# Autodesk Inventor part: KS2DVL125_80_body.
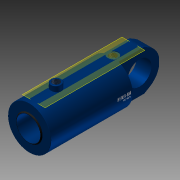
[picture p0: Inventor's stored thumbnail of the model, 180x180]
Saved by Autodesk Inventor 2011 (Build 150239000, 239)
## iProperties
Created: 2010-11
Document SubType Name: Modeling
Designer: TB
Mass: 405.061 g
Surface Area: 916.939 cm^2
Volume: 405.061 cm^3
Density: 1 g/cm^3
Author: TB
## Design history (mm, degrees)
sketch "Sketch2"
  geometry: L1 (-35, -3)-(-35, 3); L2 (-35, -9)-(-35, 9); L3 (-35, 0)-(-35, 72.5); L4 (-35, 72.5)-(-300, 72.5); L5 (-300, 72.5)-(-300, 72.5); L6 (-300, 72.5)-(-310, 72.5); L7 (-310, 72.5)-(-310, 44); L8 (-310, 44)-(-313, 41); L9 (-313, 41)-(-313, 40); L10 (-313, 40)-(-218, 40); L11 (-218, 40)-(-218, 62.5); L12 (-218, 62.5)-(-66, 62.5); L13 (-66, 62.5)-(-66, 0); L14 (-66, 0)-(-35, 0); L15 (-66, 0)-(-148.421, 0); L16 (-35, 9)-(-32, 12) reference; L17 (-32, 12)-(-35, 12) reference; L18 (-35, 12)-(-35, 9) reference; L19 (-32, 12)-(-35, 9) reference; L20 (-32, 12)-(-35, 12) reference; L21 (-35, 9)-(-35, 12) reference; L22 (-35, 9)-(-32, 12) reference; 1 further point
  constraints: 44 end point, 8 perpendicular, 6 parallel, 5 collinear, 2 horizontal, 2 vertical, 1 coincident, 1 midpoint, 1 point on line, 10 other
  dimensions: "DiaY" = 145 diameter of L4 L15; "DiaI" = 125 diameter of L12 L15; "d4" = 1 distance of L8.end L9.end; "d5" = 45 deg angle of L10 L8; "d6" = 3 distance between parallel lines of L7 L9; "DiaStang" = 80 diameter of L10 L15; "RindDia" = 145 diameter of L6 L15; "RingLengde" = 10 distance of L5.end L6.end; "RingTykk" = 92 distance between parallel lines of L11 L7; "KroppLengde" = 275 distance between parallel lines of L7 L3 (derived); "BunnTykkelse" = 31 distance between parallel lines of L13 L3
revolve "Kropp" sketch "Sketch2" stored, may be unused: angle "d13" = 90 deg
sketch "Sketch3"
  geometry: L1 (-66, -62.5)-(-66, 62.5) reference; L2 (-66, 0.01)-(-166, 0.01); L3 (-166, -0.01)-(-66, -0.01); A1 r 0.01 centre (-166, 0) between (-166, 0.01) and (-166, -0.01); A2 r 0.01 centre (-66, 0) between (-66, -0.01) and (-66, 0.01); 2 further points
  constraints: 4 end point, 4 point on circle, 4 tangent, 2 centre point, 1 coincident, 1 midpoint, 1 parallel, 1 perpendicular
  dimensions: "d17" = 0.01 radius of A2; "d18" = 100 distance of L2.start L2.end (= Slaglengde)
feature "BaneTransitionalConstraint" sketch "Sketch3" dims "d19" = 2, "d20" = 0
sketch "Sketch6"
  geometry: L1 (-101.5, 0)-(101.5, 0) reference; L2 (14.671, 71)-(-11.843, 71); L3 (72.5, 0)-(72.5, 31.248); L4 (-72.5, 0)-(-72.5, -18.451); A1 r 72.5 centre (0, 0) between (-72.5, 0) and (72.5, 0) reference; 2 further points
  constraints: 6 end point, 2 point on circle, 2 vertical, 2 other
  dimensions: "d30" = 71 distance from line of point (0, 0) L2 (computed from DiaY); "d31" = 0 deg angle of L1 L2 (computed from Vinkel_Plussport); "d37" = 90 deg angle of L2 L3; "d38" = 90 deg angle of L2 L4
  node "Projected Loop3"
workplane "Work Plane5"
sketch "Sketch7"
  geometry: L1 (14.671, -375.6)-(14.671, 62.6) reference; L2 (-19.633, -35)-(38.367, -35) reference; C1 r 17.5 at (14.671, -52.5); 1 further point
  constraints: 1 centre point, 1 point on line
  dimensions: "PortDia" = 35 diameter of C1
extrude "Extrusion2" cut sketch "Sketch7" stored distance "d34" = 1.5; taper "d35" = 0 deg
workplane "Work Plane7"
sketch "Sketch4"
  geometry: L1 (-16.68, -40)-(-16.68, -78.777); L2 (-16.68, -78.777)-(16.68, -78.777); L3 (16.68, -78.777)-(16.68, -40); L4 (16.68, -40)-(-16.68, -40); L5 (-40.643, -40)-(0, -40); L6 (-29, -35)-(29, -35); L7 (0, -35)-(0, -40); 2 further points
  constraints: 6 end point, 2 midpoint, 2 other
  dimensions: "d40" = 5 distance of L7.start L5.end
emboss "Emboss1" sketch "Sketch4" dims "d4" = 1, "d5" = 45 deg, "d6" = 3, "d22" = 0.2, "d23" = 0, "DiaI" = 125, "DiaY" = 145, "RindDia" = 145, "DiaStang" = 80, "RingTykk" = 92, "RingLengde" = 10, "KroppLengde" = 275 (derived), "BunnTykkelse" = 31
workplane "Work Plane8"
sketch "Sketch8"
  geometry: L1 (-29, -35)-(29, -35); L2 (0, -35)-(0, -40); L3 (-5.906, -110.587)-(-5.906, -40); L4 (-5.906, -40)-(5.906, -40); L5 (5.906, -40)-(5.906, -110.587); L6 (5.906, -110.587)-(-5.906, -110.587); L7 (72.5, -35)-(-72.5, -35); L8 (72.5, -35)-(-72.5, -35) reference; 3 further points
  constraints: 6 end point, 4 midpoint, 2 other
  dimensions: "d42" = 5 distance of L2.start L2.end
emboss "Emboss2" sketch "Sketch8" dims "d4" = 1, "d5" = 45 deg, "d6" = 3, "d43" = 0.2, "d44" = 0, "DiaI" = 125, "DiaY" = 145, "RindDia" = 145, "DiaStang" = 80, "RingTykk" = 92, "RingLengde" = 10, "KroppLengde" = 275 (derived), "BunnTykkelse" = 31
sketch "Sketch9"
  geometry: A1 r 12.5 centre (9.367, -52.5) between (0, -60.776) and (18.735, -60.776) reference; 1 further point
hole "Hole1" sketch "Sketch9" at (9.367, -52.5) diameter "d45" = 14.95; stored, may be unused: countersink angle "d49" = 82 deg, drill point angle "d51" = 118 deg; dims "d46" = 6, "d47" = 3.023, "d48" = 2, "DiaInvPluss" = 24.5
workplane "Work Plane9"
sketch "Sketch10"
  geometry: L1 (-101.5, 0)-(101.5, 0) reference; L2 (0, 72.5)-(13.136, 72.5); L3 (0, 72.5)-(0, 31.79); L4 (17.5, 70.356)-(17.5, 90); L5 (17.5, 90)-(0, 90); L6 (0, 90)-(0, 72.5); L7 (0, 72.5)-(17.5, 70.356); C1 r 72.5 at (0, 0) reference; A1 r 72.5 centre (0, 0) between (0, 72.5) and (17.5, 70.356); 1 further point
  constraints: 12 end point, 4 perpendicular, 2 concentric, 2 point on circle, 1 centre point, 1 point on line, 1 tangent
  dimensions: "d53" = 0 deg angle of L1 L2 (computed from Vinkel_Minusport); "DiaUtvStussMinus" = 35 diameter of L4 L3; "HøydeStussMinuss" = 17.5 distance between parallel lines of L2 L5
revolve "Revolution2" sketch "Sketch10" stored, may be unused: angle "d56" = 90 deg
hole "Hole2" diameter "d59" = 24.117; stored, may be unused: countersink angle "d63" = 82 deg, drill point angle "d65" = 118 deg; dims "d57" = 10, "d58" = 10, "d60" = 6, "d61" = 3.023, "d62" = 2, "DiaInvStussMinus" = 24.5
fillet "Fillet1" dims "d66" = 2
sketch "Sketch15"
  geometry: L1 (25, -68.053)-(25, 68.053); L2 (-25, -68.053)-(-25, 68.053); L3 (0, 101.5)-(0, -101.5) reference; A1 r 72.5 centre (0, 0) between (25, -68.053) and (-25, -68.053) reference; A2 r 72.5 centre (0, 0) between (25, 68.053) and (-25, 68.053); A3 r 72.5 centre (0, 0) between (-25, -68.053) and (25, -68.053)
  constraints: 8 point on circle, 4 end point, 4 point on line, 2 centre point, 2 concentric, 2 parallel, 1 coincident
  dimensions: "EyeBunnTykk" = 25 distance from line of L1 A1.centre; "EyeBunnTykk2" = 25 distance from line of A1.centre L2
extrude "Extrusion6" join sketch "Sketch15" taper "d98" = 0 deg; distance "LengdeEyeMinussBunntykk" = 136
sketch "Sketch16"
  geometry: L1 (-309, 72.5)-(101, 72.5) reference; L2 (-309, -72.5)-(101, -72.5) reference; L3 (-309, 72.5)-(101, 72.5) reference; L4 (101, 72.5)-(101, 68.053) reference; L5 (101, -68.053)-(101, 68.053) reference; L6 (-393.672, 0)-(199.03, 0) reference; L7 (36.5, 72.5)-(101, 72.5); L8 (101, 72.5)-(101, 8); A1 r 64.5 centre (36.5, 8) between (101, 8) and (36.5, 72.5); 6 further points; 2 other entities
  constraints: 4 end point, 4 tangent, 2 point on circle, 2 point on line, 1 centre point, 1 collinear, 1 perpendicular, 2 other
  dimensions: "d137" = 8 distance from line of L8.end L6
extrude "Extrusion7" cut sketch "Sketch16" taper "d102" = 0 deg; stored distance "ExtruEyeBunn" = 50
mirror "Mirror1"
sketch "Sketch20"
  geometry: L1 (-309, 72.5)-(101, 72.5) reference; L2 (101, -68.053)-(101, 68.053) reference; L3 (101, 72.5)-(101, 68.053) reference; L4 (-391.89, 0)-(188.338, 0) reference; L5 (-35, -68.053)-(-35, 68.053) reference; L6 (-35, 0)-(36, 0); L7 (36, 0)-(36, 20.918); L8 (69.354, 57.771)-(50.804, 68.481); A1 r 66.708 centre (36, 0) between (101, 15) and (69.354, 57.771); A2 r 35 centre (43.843, 37.5) between (43.843, 72.5) and (43.843, 72.5); A3 r 30 centre (35.804, 42.5) between (50.804, 68.481) and (35.804, 72.5); 1 further point
  constraints: 6 end point, 6 point on circle, 5 point on line, 4 tangent, 3 centre point, 1 coincident, 1 midpoint, 1 perpendicular
  dimensions: "d147" = 71 distance of L6.start L6.end; "d157" = 15 distance from line of L4 A1.start; "d158" = 30 deg angle of L1 L8; "d160" = 30 radius of A3
extrude "Extrusion10" cut sketch "Sketch20" stored distance "d144" = 10; taper "d145" = 0 deg
mirror "Mirror2"
sketch "Sketch17"
  geometry: L1 (136.107, 0)-(0, 0) reference; L2 (68.053, -360.8)-(68.053, 218.8) reference; C1 r 40 at (68.053, 71); 1 further point
  constraints: 1 centre point, 1 point on line
  dimensions: "DiaHullEyeBunn" = 80 diameter of C1; "d125" = 71 distance from line of C1.centre L1
extrude "Extrusion8" cut sketch "Sketch17" taper "d105" = 0 deg; distance "ExtruHullEye" = 50
pattern_circular "Circular Pattern1 Only Subsea" dims "d108" = 180 deg (derived)
workplane "Work Plane11"
sketch "Sketch18"
  geometry: L1 (0, -79.2)-(0, 13.2) reference; L2 (62.5, -66)-(-62.5, -66) reference; L3 (62.5, -66)-(-62.5, -66) reference; C1 r 17.5 at (0, -29); 1 further point
  constraints: 1 centre point
  dimensions: "DiaForsenkPlussPort" = 35 diameter of C1; "PlassPlussport" = 37 distance from line of L2 C1.centre
extrude "Extrusion9" cut sketch "Sketch18" stored distance "d113" = 10; taper "d114" = 0 deg
sketch "Sketch19"
  geometry: 10 further points
  constraints: 1 other
hole "Hole3" sketch "Sketch19" at (0, -29) diameter "d115" = 24.117; stored, may be unused: countersink angle "d119" = 90 deg, drill point angle "d121" = 118 deg; dims "d116" = 6, "d117" = 4, "d118" = 2, "d120" = 14.5
pattern_circular "Circular Pattern2 Only Subsea" dims angle "d123" = 360 deg
body "Solid1"
chamfer "Chamfer" distance "Chamfer" = 1; stored, may be unused: second distance "d15" = 2, angle "d16" = 45 deg
node "Projected Loop2"
body "Srf1"
node "Projected Loop10"
other parameters: "Slaglengde" = 100, "Forlengelse_rør" = 0, "Vinkel_Plussport" = 0 [user parameter; used in 1 equation term], "Vinkel_Minusport" = 0, "d32" = 90 deg, "d39" = 90 deg, "d41" = 90 deg, "Minusport2" = 180 deg, "ForsenkningPlussPort" = 70.7 (derived), "EyeLengdeUBunn" = 136
